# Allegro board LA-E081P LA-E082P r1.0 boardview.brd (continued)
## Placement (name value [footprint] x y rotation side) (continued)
CZ121  470P_0402_50V7K  [C_0402]  270.52 48.23 270 top
CZ122  0.1U_0201_10V6K  [C_0201]  192.96 14.5 180 top
CZ124  2200P_0402_50V7K  [C_0402]  277.32 47.39 180 bottom
CZ125  0.1U_0201_10V6K  [C_0201]  277.25 73.39 90 top
CZ126  220P_0402_50V7K  [C_0402]  275.72 71.09 270 top
CZ127  1000P_0402_50V7K  [C_0402]  274.71 71.09 270 top
CZ128  0.1U_0201_10V6K  [C_0201]  272.93 73.55 90 top
CZ129  0.1U_0201_10V6K  [C_0201]  279.95 39.96 180 bottom
CZ130  470P_0402_50V7K  [C_0402]  281.31 41.5 270 bottom
CZ133  0.1U_0201_10V6K  [C_0201]  289.18 62.63 90 bottom
CZ134  0.01UF_0402_25V7K  [C_0402]  283.8 66.95 180 top
CZ135  0.22U_0402_10V6K  [C_0402]  282.88 65.99 0 top
CZ136  0.22U_0402_10V6K  [C_0402]  282.88 65.04 0 top
CZ141  0.22U_0402_10V6K  [C_0402]  282.88 63.14 0 top
CZ142  0.22U_0402_10V6K  [C_0402]  282.88 64.09 0 top
CZ197  470P_0402_50V7K  [C_0402]  270.69 53.36 0 top
CZ198  100P_0402_50V8J  [C_0402]  291.47 50.51 270 top
DA1  AZ5123-02S.R7G_SOT23-3  [L03ESDL5V0CC3-2_SOT23-3]  311.82 35.07 90 top
DA2  -  [L03ESDL5V0CC3-2_SOT23-3]  311.82 31.01 90 top
DA3  AZ5123-02S.R7G_SOT23-3  [L03ESDL5V0CC3-2_SOT23-3]  309.73 39.13 270 top
DA6  -  [L03ESDL5V0CC3-2_SOT23-3]  284.08 29.74 270 top
DA7  -  [L03ESDL5V0CC3-2_SOT23-3]  284.08 34.31 270 top
DA8  RB751S40T1G_SOD523-2  [RB520SM-30T2R_EMD2-2]  293.81 42.02 0 top
DE1  RB751S40T1G_SOD523-2  [RB520SM-30T2R_EMD2-2]  267.18 39.09 220 top
DI1  -  [L05ESDL5V0NA-4_SLP2510P8-10-9]  19.94 70.38 270 top
DI2  -  [AZC199-02SPR7G_SOT23-3]  24.14 71.27 270 top
DI3  -  [AZC199-02SPR7G_SOT23-3]  80.46 101.72 180 bottom
DI4  -  [L05ESDL5V0NA-4_SLP2510P8-10-9]  308.81 54.87 90 top
DI5  -  [AZC199-02SPR7G_SOT23-3]  309.12 50.82 180 top
DI6  -  [L05ESDL5V0NA-4_SLP2510P8-10-9]  80.41 102.2 180 top
DT1  -  [1N4148WS-7-F_SOD323-2]  38.67 98.57 180 bottom
DT2  -  [1N4148WS-7-F_SOD323-2]  38.67 96.79 180 bottom
DT3  -  [1N4148WS-7-F_SOD323-2]  35.69 94.45 270 bottom
DT4  -  [L30ESD24VC3-2_SOT23-3]  12.83 90.21 0 bottom
DT5  ESD8011MUT5G_X3DFN2-2  [ESD8011MUT5G_X3DFN2-2-S]  11.86 94.2 270 bottom
DT6  ESD8011MUT5G_X3DFN2-2  [ESD8011MUT5G_X3DFN2-2-S]  11.86 95.04 90 bottom
DT7  ESD8011MUT5G_X3DFN2-2  [ESD8011MUT5G_X3DFN2-2-S]  11.85 94.31 270 top
DT8  ESD8011MUT5G_X3DFN2-2  [ESD8011MUT5G_X3DFN2-2-S]  11.83 97.85 90 top
DT9  ESD8011MUT5G_X3DFN2-2  [ESD8011MUT5G_X3DFN2-2-S]  11.83 100.05 270 bottom
DT10  ESD8011MUT5G_X3DFN2-2  [ESD8011MUT5G_X3DFN2-2-S]  11.83 100.9 90 bottom
DT11  ESD8011MUT5G_X3DFN2-2  [ESD8011MUT5G_X3DFN2-2-S]  11.86 97.03 270 bottom
DT12  ESD8011MUT5G_X3DFN2-2  [ESD8011MUT5G_X3DFN2-2-S]  11.83 97.85 90 bottom
DT13  ESD8011MUT5G_X3DFN2-2  [ESD8011MUT5G_X3DFN2-2-S]  11.4 91.42 270 bottom
DT14  ESD8011MUT5G_X3DFN2-2  [ESD8011MUT5G_X3DFN2-2-S]  11.4 92.26 90 bottom
DT15  ESD8011MUT5G_X3DFN2-2  [ESD8011MUT5G_X3DFN2-2-S]  11.86 97.03 270 top
DT16  ESD8011MUT5G_X3DFN2-2  [ESD8011MUT5G_X3DFN2-2-S]  11.86 95.04 90 top
DT17  ESD8011MUT5G_X3DFN2-2  [ESD8011MUT5G_X3DFN2-2-S]  11.83 100.9 90 top
DT18  ESD8011MUT5G_X3DFN2-2  [ESD8011MUT5G_X3DFN2-2-S]  11.83 100.05 270 top
DT19  ESD8011MUT5G_X3DFN2-2  [ESD8011MUT5G_X3DFN2-2-S]  11.85 92.26 90 top
DT20  ESD8011MUT5G_X3DFN2-2  [ESD8011MUT5G_X3DFN2-2-S]  11.84 91.42 270 top
DV1  -  [BAT54CW_SOT323-3]  105.67 86.12 180 bottom
DV2  -  [BAT54CW_SOT323-3]  103.13 85.87 180 bottom
DV3  -  [BAT54CW_SOT323-3]  92.97 83.78 0 bottom
DV4  -  [AZC199-02SPR7G_SOT23-3]  116.44 87.33 90 bottom
DV5  -  [PJDLC05C_SOT23-3]  314.3 85.04 90 bottom
DV6  -  [PJDLC05C_SOT23-3]  314.3 80.98 90 bottom
DZ1  RB751S40T1G_SOD523-2  [RB520SM-30T2R_EMD2-2]  216.57 9.38 180 top
DZ2  RB751S40T1G_SOD523-2  [RB520SM-30T2R_EMD2-2]  216.57 10.65 180 top
DZ5  RB751S40T1G_SOD523-2  [RB520SM-30T2R_EMD2-2]  292.83 49.17 90 top
DZ6  RB751S40T1G_SOD523-2  [RB520SM-30T2R_EMD2-2]  293.53 45.75 90 top
DZ7  RB751S40T1G_SOD523-2  [RB520SM-30T2R_EMD2-2]  221.31 22.52 180 top
FD1  FIDUCIAL MARK~D  [FIDUCIAL_C40M80]  315.36 95.48 0 top
FD2  FIDUCIAL MARK~D  [FIDUCIAL_C40M80]  15.37 3.83 0 top
FD3  FIDUCIAL MARK~D  [FIDUCIAL_C40M80]  15.37 3.83 180 bottom
FD4  FIDUCIAL MARK~D  [FIDUCIAL_C40M80]  323.22 97.3 180 bottom
H1  -  [H_3P8]  87.65 73.4 0 top
H2  -  [H_3P8]  87.65 45.4 0 top
H3  -  [H_3P8]  144.25 81.75 0 top
H4  -  [H_3P8]  149.15 47.45 0 top
H5  -  [H_1P1N]  98.5 71.86 0 top
H6  -  [H_1P1N]  139.62 48.75 0 top
H7  -  [H_3P2]  234.9 15.5 0 top
H8  -  [H_3P2]  296.05 87.5 0 top
H9  H_2P3  [H_2P3-G]  141.95 118.9 0 top
H10  H_3P0  [H_3P0-G]  310.15 98.9 0 top
H12  H_2P5  [H_2P5-G]  323.65 22.4 0 top
H14  H_4P0  [H_4P0-G]  267.65 58.9 0 top
H15  H_4P0  [H_4P0-G]  269.65 101.4 0 top
H16  H_2P3  [H_2P3-G]  67.35 116.9 0 top
H17  H_4P0  [H_4P0-G]  113.15 2.1 0 top
H18  H_2P5  [H_2P5-G]  4.45 3 0 top
H20  H_4P0  [H_4P0-G]  202.75 37.1 0 top
H22  H_4P0  [H_4P0-G]  241 1.5 0 top
H23  H_2P5  [H_2P5-G]  6.25 106.1 0 top
H24  H_2P5  [H_2P5-G]  6.25 88 0 top
H25  H_2P2  [H_2P2-G]  4.45 8.4 0 top
H26  H_2P3  [H_2P3-G]  116.55 116.9 0 top
H28  H_2P5  [H_2P5-G]  268.15 106.3 0 top
H29  H_2P5  [H_2P5-G]  282.15 110.4 0 top
H32  H_2P6X3P6  [H_2P6X3P6-G]  318.05 22.4 90 top
H34  -  [H_3P2]  89.35 94.4 0 top
H35  -  [H_3P2]  123.75 94.4 0 top
H38  -  [H_3P8]  147.55 117.4 0 top
H42  -  [H_0P7N]  121.59 116.25 0 top
H43  -  [H_0P9N]  130.79 103.2 0 top
JAPS1  ACES_50506-01841-P01  [ACES_50506-01841-P01_18P]  317.63 62.25 90 bottom
JCRT1  CCM_C070546HR015M29CZR  [CCM_C070546HR015M29CZR_15P-T]  322.15 83.18 90 bottom
JDB1  JXT_FP241AH-006GAAM  [JXT_FP241AH-006GAAM_6P]  32.37 97.09 180 top
JDEG1  JXT_FP241AH-010GAAM  [JXT_FP241AH-010GAAM_10P]  275.98 77.9 270 bottom
JDIMM1  LCN_DAN05-Q0406-0103  [LCN_DAN05-Q0406-0103_260P]  39.28 13 180 bottom
JDIMM2  LCN_DAN05-Q0406-0103  [LCN_DAN05-Q0406-0103_260P]  120.28 13 180 bottom
JEDP1  ACES_50398-04041-001  [ACES_50398-04041-001_40P]  116.3 92.14 180 bottom
JESPI  JXT_FP241AH-010GAAM  [JXT_FP241AH-010GAAM_10P]  269.76 70.34 270 bottom
JFAN1  ACES_50271-0040N-001  [ACES_50271-0040N-001_4P]  267.69 44.49 50 bottom
JHDMI1  CONCR_099BKAC19YBLCNF  [CONCR_099BKAC19YBLCNF_19P]  98.55 111.32 0 bottom
JHP1  SINGA_2SJ3095-136111F  [SINGA_2SJ3095-136111F_7P-T]  316.45 38.4 90 bottom
JIR1  ACES_50208-0060N-P01  [ACES_50208-0060N-P01_6P]  76.83 92.5 90 bottom
JKBTP1  CVILU_CF5020FD0RK-05-NH  [CVILU_CF5020FD0RK-05-NH_20P-T]  213.13 22.65 270 top
JLED1  CVILU_CF5006FD0R0-05-NH  [CVILU_CF5006FD0R0-05-NH_6P]  284.4 51.15 0 top
JLOM1  SANTA_130456-831  [SANTA_130456-831_13P-T]  292.98 107.18 0 bottom
JNGFF1  BELLW_80148-4221  [BELLW_80148-4221_67P]  201.27 24.75 270 bottom
JNGFF2  BELLW_80149-4221  [BELLW_80149-4221_67P]  286.8 41.87 0 bottom
JNGFF3  LCN_DAN05-67356-0103  [LCN_DAN05-67356-0103_75P]  307.95 33.92 180 bottom
JRTC1  ACES_50271-0020N-001  [ACES_50271-0020N-001_2P]  61.25 78.28 90 bottom
JSATA1  ACES_59003-02006-002  [ACES_59003-02006-002_20P]  271.9 34.63 0 bottom
JSD1  T-SOL_156-2000302608_NR  [T-SOL_156-2000302608_19P_NR]  32.38 40.5 90 bottom
JSIM1  T-SOL_5-991503004000-6  [T-SOL_5-991503004000-6_8P-T]  123.74 105.88 0 bottom
JSPI1  E-T_6705K-Y20N-00L  [E-T_6705K-Y20N-00L_20P]  157.85 46.93 180 bottom
JSPK1  ACES_50278-00401-001  [ACES_50278-00401-001_4P]  264.99 29.6 90 top
JTAG1  @SHORT PADS~D  [SHORTPADS]  299.73 87.62 90 top
JUART1  CVILU_CI1804M1VRA-NH  [CVILU_CI1804M1VRA-NH_4P]  45.26 62.29 270 bottom
JUSB1  C-K_26230A-8K1A-02  [C-K_26230A-8K1A-02_9P-T]  313.1 46.35 270 bottom
JUSB2  LOTES_AUSB0014-P003A  [LOTES_AUSB0014-P003A_9P]  15.66 77.9 90 bottom
JUSB3  C-K_26210B-8K1A-02  [C-K_26210B-8K1A-02_9P]  84.05 107.02 0 bottom
JUSBC1  JAE_DX07BD24JJ2  [JAE_DX07BD24JJ2_24P-T]  7.55 94.43 90 bottom
JUSH1  CVILU_CF5026FD0RK-05-NH  [CVILU_CF5026FD0RK-05-NH_26P-T]  222.97 7.15 90 top
JXDP1  SAMTE_BSH-030-01-L-D-A  [SAMTE_BSH-030-01-L-D-A_60P]  75.45 35.84 180 top
LA5  BLM15PX600SN1D_2P  [MURAT_BLM15PX600SN1D_2P]  307.54 28.57 270 top
LA6  BLM15PD800SN1D_2P  [MURAT_BLM15PD800SN1D_2P]  288.86 30.05 180 top
LA7  BLM15PD800SN1D_2P  [MURAT_BLM15PD800SN1D_2P]  288.86 31.13 180 top
LA8  BLM15PD800SN1D_2P  [MURAT_BLM15PD800SN1D_2P]  288.87 36.76 270 top
LA9  BLM15PD800SN1D_2P  [MURAT_BLM15PD800SN1D_2P]  286.89 36.85 180 top
LA10  BLM15PX330SN1D_2P  [MURAT_BLM15PX330SN1D_2P]  309.38 39.13 0 bottom
LA11  BLM15PX330SN1D_2P  [MURAT_BLM15PX330SN1D_2P]  309.38 36.59 0 bottom
LA12  BLM15PX600SN1D_2P  [MURAT_BLM15PX600SN1D_2P]  294.5 32.78 180 top
LA13  HCB2012VF-601T20_2P  [TAI-T_HCB2012VF-601T20_2P]  300.17 43.47 90 top
LA14  BLM15PX600SN1D_2P  [MURAT_BLM15PX600SN1D_2P]  293.46 40.95 0 top
LA15  BLM15PX330SN1D_2P  [MURAT_BLM15PX330SN1D_2P]  308.02 37.41 90 top
LA16  BLM15PX330SN1D_2P  [MURAT_BLM15PX330SN1D_2P]  307.99 36.54 270 top
LC1  BLM15GA750SN1D_2P  [MURAT_BLM15GA750SN1D_2P]  126.5 33.4 270 top
LC2  BLM15GA750SN1D_2P  [MURAT_BLM15GA750SN1D_2P]  145.29 62.44 180 top
LED3  LTW-C193DC-C_WHITE  [LED_LTW-C193DC-C_2P]  320.9 98.51 180 top
LGA1  -  [LNG2DMTR_LGA12_2X2]  273.72 45.23 270 bottom
LI3  EXC24CQ900U_4P  [PANAS_EXC24CQ900U_4P]  29.72 69.87 270 top
LI4  EXC24CQ900U_4P  [PANAS_EXC24CQ900U_4P]  77.35 100.09 270 bottom
LI7  EXC24CQ900U_4P  [PANAS_EXC24CQ900U_4P]  308.44 45.62 180 top
LI8  MCM1012B900F06BP_4P  [INPAQ_MCM1012B900F06BP_4P]  290.2 45.6 270 top
LI9  MCM1012B900F06BP_4P  [INPAQ_MCM1012B900F06BP_4P]  197.57 23.64 0 bottom
LI16  HCM1012GH900BP_4P  [INPAQ_HCM1012GH900BP_4P]  292.23 45.6 270 top
LI17  HCM1012GH900BP_4P  [INPAQ_HCM1012GH900BP_4P]  295.4 47.57 270 top
LL1  4.7UH_BRC2012T4R7MD_20%  [TAIYO_BRC2012T4R7MD_2P]  283.56 86.38 0 top
LT11  BLM15PX600SN1D_2P  [MURAT_BLM15PX600SN1D_2P]  19.69 89.05 90 top
LV1  BLM15PX221SN1D_2P  [MURAT_BLM15PX221SN1D_2P]  106.94 88.9 270 bottom
LV3  HCM1012GH900BP_4P  [TAIYO_MCF12102G900-T_4P-NPM]  98.41 104.23 90 top
LV6  HCM1012GH900BP_4P  [TAIYO_MCF12102G900-T_4P-NPM]  101.96 104.23 90 top
LV9  HCM1012GH900BP_4P  [TAIYO_MCF12102G900-T_4P-NPM]  108.31 104.23 90 top
LV12  HCM1012GH900BP_4P  [TAIYO_MCF12102G900-T_4P-NPM]  105.52 104.23 90 top
LV14  BLM15PX600SN1D_2P  [MURAT_BLM15PX600SN1D_2P]  275.6 55.39 90 bottom
LV16  BLM15BB470SN1D_2P  [MURAT_BLM15BB470SN1D_2P]  317.38 89.48 270 bottom
LV17  BLM15BB470SN1D_2P  [MURAT_BLM15BB470SN1D_2P]  316.11 89.48 270 bottom
LV18  BLM15BB470SN1D_2P  [MURAT_BLM15BB470SN1D_2P]  313.44 76.01 90 bottom
LV19  BLM15AG121SN1D_L0402_2P  [MURAT_BLM15AG121SN1D_L0402_2P]  316.62 77.76 90 top
LV20  BLM15AG121SN1D_L0402_2P  [MURAT_BLM15AG121SN1D_L0402_2P]  316.62 75.47 90 top
LV27  EXC24CQ900U_4P  [PANAS_EXC24CQ900U_4P]  120.66 86.27 270 bottom
LV30  BLM15PX600SN1D_2P  [MURAT_BLM15PX600SN1D_2P]  281.72 56.08 270 top
LZ1  EXC24CQ900U_4P  [PANAS_EXC24CQ900U_4P]  110.88 87.52 0 bottom
NOREF  -  []  323.65 22.4 0 top
NOREF#2  -  []  186.38 29.29 0 top
NOREF#3  -  []  4.45 8.4 0 top
NOREF#4  -  []  141.95 118.9 0 top
NOREF#5  -  []  87.65 73.4 0 top
NOREF#6  -  []  113.15 2.1 0 top
NOREF#7  -  []  296.05 87.5 0 top
NOREF#8  -  []  6.25 106.1 0 top
NOREF#9  -  []  6.25 88 0 top
NOREF#10  -  []  65.41 -32.24 0 top
NOREF#11  -  []  168.09 76.17 0 top
NOREF#12  -  []  89.63 31.42 0 top
NOREF#13  -  []  282.15 110.4 0 top
NOREF#14  -  []  147.55 117.4 0 top
NOREF#15  -  []  108.27 26.24 90 top
NOREF#16  -  []  72.27 161.56 0 top
NOREF#17  -  []  4.45 3 0 top
NOREF#18  -  []  310.15 98.9 0 top
NOREF#19  -  []  144.25 81.75 0 top
NOREF#20  -  []  145.04 20.91 0 top
NOREF#21  -  []  317.55 22.4 0 top
NOREF#22  -  []  87.44 26.31 0 top
NOREF#23  -  []  149.15 47.45 0 top
NOREF#24  -  []  67.35 116.9 0 top
NOREF#25  -  []  116.55 116.9 0 top
NOREF#26  -  []  234.9 15.5 0 top
NOREF#27  -  []  4.45 8.4 0 top
NOREF#28  -  []  4.45 8.4 0 top
NOREF#29  -  []  269.65 101.4 0 top
NOREF#30  -  []  41.75 18.36 0 top
NOREF#31  -  []  268.15 106.3 0 top
NOREF#32  -  []  202.75 37.1 0 top
NOREF#33  -  []  267.65 58.9 0 top
NOREF#34  -  []  87.65 45.4 0 top
NOREF#35  -  []  241 1.5 0 top
NOREF#36  -  []  81.58 28.4 180 bottom
NOREF#37  -  []  171.96 86.63 180 bottom
NOREF#38  -  []  129.42 24.4 180 bottom
PBATT1  DEREN_40-42251-01001RHF  [DEREN_40-42251-01001RHF_10P-T]  26 12.35 180 bottom
PC1  2200P_0402_50V7K  [C_0402]  22.61 7.46 270 top
PC2  2200P_0402_50V7K  [C_0402]  63.01 78.98 270 top
PC3  1U_0603_25V6K  [C_0603]  58.39 77.53 90 top
PC4  0.022U_0603_50V7K  [C_0603]  46.77 80.85 0 top
PC5  1000P_0603_50V7K  [C_0603]  54.62 87.74 180 bottom
PC6  0.022U_0603_50V7K  [C_0603]  48.98 91.17 0 top
PC7  0.1U_0603_25V7K  [C_0603]  53.78 89.06 270 top
PC8  10U_0805_25V6K  [C_0805]  52.3 86.08 0 top
PC9  0.1U_0402_10V7K  [C_0402]  61.84 96.75 90 bottom
PC10  2.2U_0402_10V6M  [C_0402]  73.78 104.73 0 top
PC11  1U_0603_50V6K  [C_0603]  73.84 100.89 0 top
PC100  100P_0402_50V8J  [C_0402]  157.25 117.58 180 bottom
PC102  0.1U_0603_25V7K  [C_0603]  159.77 110.25 180 top
PC103  100P_0402_50V8J  [C_0402]  157.26 117.58 180 top
PC104  10U_0805_25V6K  [C_0805]  157.19 115.59 180 bottom
PC105  10U_0805_25V6K  [C_0805]  157.19 115.59 180 top
PC106  22UF_0805_6.3V6M  [C_0805]  149.36 106.44 90 bottom
PC107  22UF_0805_6.3V6M  [C_0805]  151.14 104.26 90 bottom
PC108  22UF_0805_6.3V6M  [C_0805]  152.85 104.26 90 top
PC109  22UF_0805_6.3V6M  [C_0805]  149.36 106.44 90 top
PC110  22UF_0805_6.3V6M  [C_0805]  152.85 104.26 90 bottom
PC111  4.7U_0603_6.3V6K  [C_0603]  154.27 109.06 180 top
PC112  680P_0603_50V7K  [C_0603]  160.57 108.73 270 bottom
PC113  1000P_0402_50V7K  [C_0402]  152.45 112.46 180 top
PC114  0.1U_0603_25V7K  [C_0603]  162.33 112 0 bottom
PC115  100P_0402_50V8J  [C_0402]  163.38 117.53 90 bottom
PC116  100P_0402_50V8J  [C_0402]  163.33 117.63 90 top
PC117  10U_0805_25V6K  [C_0805]  164.43 117.99 0 bottom
PC118  10U_0805_25V6K  [C_0805]  164.47 118.1 0 top
PC119  4.7U_0603_6.3V6K  [C_0603]  170.63 111.65 0 bottom
PC120  22UF_0805_6.3V6M  [C_0805]  170.95 101.06 0 top
PC121  22UF_0805_6.3V6M  [C_0805]  170.92 102.84 0 top
PC122  22UF_0805_6.3V6M  [C_0805]  170.95 104.59 0 top
PC123  22UF_0805_6.3V6M  [C_0805]  171.24 101.05 0 bottom
PC124  22UF_0805_6.3V6M  [C_0805]  171.24 102.82 0 bottom
PC125  680P_0603_50V7K  [C_0603]  162.5 106.76 270 bottom
PC126  4.7U_0603_6.3V6K  [C_0603]  170.63 112.86 0 bottom
PC127  1000P_0402_50V7K  [C_0402]  171.17 114.63 0 bottom
PC128  4.7U_0402_6.3V6M  [C_0402]  171.03 115.5 90 bottom
PC129  22UF_0805_6.3V6M  [C_0805]  151.14 104.26 90 top
PC130  22UF_0805_6.3V6M  [C_0805]  171.24 104.6 0 bottom
PC131  82P_0402_50V8J  [C_0402]  157.24 118.53 180 bottom
PC132  82P_0402_50V8J  [C_0402]  164.23 119.33 180 bottom
PC200  10U_0805_25V6K  [C_0805]  42.31 47.63 90 bottom
PC201  10U_0805_25V6K  [C_0805]  42.98 47.6 90 top
PC202  0.1U_0402_25V6  [C_0402]  40.7 47.89 90 bottom
PC203  2200P_0402_50V7K  [C_0402]  40.76 47.87 90 top
PC204  680P_0603_50V7K  [C_0603]  47.51 48.98 180 top
PC205  0.1U_0603_16V7K  [C_0603]  49.63 47.44 0 top
PC206  1U_0402_6.3V6K  [C_0402]  47.55 45.63 270 bottom
PC207  2.2U_0402_6.3V6M  [C_0402]  46.69 45.64 270 bottom
PC208  330P_0402_50V7K  [C_0402]  44.65 44.65 90 bottom
PC209  22U_0603_6.3V6M  [C_0603]  47.76 51.23 90 bottom
PC210  22U_0603_6.3V6M  [C_0603]  56.86 42.01 0 top
PC211  22U_0603_6.3V6M  [C_0603]  47.81 42.02 90 bottom
PC212  22U_0603_6.3V6M  [C_0603]  56.87 43.22 0 top
PC213  22U_0603_6.3V6M  [C_0603]  56.87 43.22 0 bottom
PC214  10U_0603_6.3V6M  [C_0603]  56.87 42.01 0 bottom
PC216  2200P_0402_50V7K  [C_0402]  56.93 44.52 0 top
PC217  100P_0402_50V8J  [C_0402]  45.55 43.79 180 bottom
PC218  1U_0402_10V6K  [C_0402]  44.98 51.14 90 bottom
PC219  22U_0603_6.3V6M  [C_0603]  46.52 51.23 90 bottom
PC221  0.1U_0402_10V7K  [C_0402]  40.59 51.15 90 bottom
PC222  0.1U_0402_10V7K  [C_0402]  43.21 51.15 90 bottom
PC223  10U_0603_6.3V6M  [C_0603]  56.86 44.42 0 bottom
PC301  100P_0402_50V8J  [C_0402]  179.13 97.43 0 top
PC302  680P_0603_50V7K  [C_0603]  174.57 91.78 90 bottom
PC303  100P_0402_50V8J  [C_0402]  179.13 97.43 0 bottom
PC304  0.1U_0603_25V7K  [C_0603]  177.87 93.17 180 bottom
PC305  10U_0603_25V6M  [C_0603]  179.2 98.51 0 top
PC306  10U_0603_25V6M  [C_0603]  179.2 98.51 0 bottom
PC307  330P_0402_50V7K  [C_0402]  185.93 93.1 90 bottom
PC308  22U_0603_6.3V6M  [C_0603]  183.39 82.12 0 bottom
PC309  22U_0603_6.3V6M  [C_0603]  183.39 80.92 0 bottom
PC310  22U_0603_6.3V6M  [C_0603]  183.39 83.33 0 bottom
PC311  22U_0603_6.3V6M  [C_0603]  183.39 79.71 0 bottom
PC312  4.7U_0603_6.3V6K  [C_0603]  184.28 91.9 0 bottom
PC313  4.7U_0603_6.3V6K  [C_0603]  184.28 90.7 0 bottom
PC314  82P_0402_50V8J  [C_0402]  179.2 99.62 0 bottom
PC401  470P_0402_50V7K  [C_0402]  137.41 107.73 0 top
PC402  0.1U_0402_25V6  [C_0402]  137.46 111.41 180 top
PC403  10U_0603_10V6M  [C_0603]  138.45 113.66 90 top
PC404  10U_0603_10V6M  [C_0603]  139.7 113.67 90 top
PC406  22U_0603_6.3V6M  [C_0603]  143.61 104.81 90 top
PC407  22U_0603_6.3V6M  [C_0603]  139.59 103.68 270 top
PC408  0.1U_0402_25V6  [C_0402]  141.69 113.37 90 top
PC409  100P_0402_50V8J  [C_0402]  140.77 113.36 90 top
PC410  470P_0402_50V7K  [C_0402]  144.71 111.42 0 top
PC411  0.1U_0402_25V6  [C_0402]  127.92 113.77 90 top
PC412  10U_0603_10V6M  [C_0603]  131.11 115.59 90 top
PC413  10U_0603_10V6M  [C_0603]  132.33 115.6 90 top
PC415  22U_0603_6.3V6M  [C_0603]  131.38 106.1 270 top
PC416  22U_0603_6.3V6M  [C_0603]  133.43 107.06 0 top
PC417  0.1U_0402_25V6  [C_0402]  130.03 116.43 180 top
PC418  2200P_0402_50V7K  [C_0402]  130.04 115.55 180 top
PC419  470P_0402_50V7K  [C_0402]  127 110.11 0 top
PC420  470P_0402_50V7K  [C_0402]  133.72 112.29 0 top
PC422  22U_0603_6.3V6M  [C_0603]  140.82 103.67 270 top
PC424  22U_0603_6.3V6M  [C_0603]  130.13 106.08 270 top
PC501  22U_0603_6.3V6M  [C_0603]  119.71 103.27 90 top
PC502  22U_0603_6.3V6M  [C_0603]  125.33 107.43 90 top
PC503  68P_0402_50V8J  [C_0402]  120.53 109.67 0 top
PC504  22U_0603_6.3V6M  [C_0603]  120.94 103.26 90 top
PC505  0.1U_0402_16V7K  [C_0402]  120.61 105.84 180 top
PC506  680P_0402_50V7K  [C_0402]  126.04 106.47 180 top
PC513  .1U_0402_16V7K  [C_0402]  197.61 3.11 270 top
PC514  4.7U_0603_6.3V6K  [C_0603]  196.56 6.33 180 top
PC515  0.01UF_0402_25V7K  [C_0402]  191.01 4.17 0 top
PC516  22U_0603_6.3V6M  [C_0603]  192.24 6.45 0 top
PC601  680P_0402_50V7K  [C_0402]  65.6 43.79 90 bottom
PC602  0.1U_0402_25V6  [C_0402]  72.04 50.72 180 bottom
PC603  1U_0603_10V6K  [C_0603]  74.37 47.96 0 top
PC604  0.22U_0603_25V7K  [C_0603]  72.65 47.92 0 bottom
PC605  47P_0402_50V8J~D  [C_0402]  74.43 52.61 270 top
PC606  100U_D_20VM_R55M  [C_D]  50.82 70.08 180 bottom
PC608  10U_0805_25V6K  [C_0805]  70.31 78.37 270 bottom
PC611  0.22U_0603_16V7K  [C_0603]  65.73 78.38 0 top
PC612  10U_0805_25V6K  [C_0805]  70.5 78.36 270 top
PC613  330P_0402_50V7K  [C_0402]  70.03 52.37 90 bottom
PC614  2200P_0402_50V7K  [C_0402]  67.39 52.37 90 bottom
PC616  68P_0402_50V8J  [C_0402]  68.25 52.32 0 bottom
PC617  1200P_0402_50V7K  [C_0402]  69.54 57.85 0 top
PC618  330P_0402_50V7K  [C_0402]  70.47 56.1 180 bottom
PC619  0.01UF_0402_25V7K  [C_0402]  70.47 55.19 180 bottom
PC620  0.082U_0402_16V7K  [C_0402]  68.64 56.04 270 top
PC621  680P_0402_50V7K  [C_0402]  71.3 56.14 270 top
PC622  680P_0603_50V7K  [C_0603]  72.55 78.19 270 top
PC624  0.033U_0402_16V7K  [C_0402]  65.99 55.18 90 bottom
PC625  330P_0402_50V7K  [C_0402]  66.5 50.91 180 bottom
PC626  0.047U_0402_25V7K  [C_0402]  66.88 55.18 90 bottom
PC627  2200P_0402_50V7K  [C_0402]  65.99 56.06 270 top
PC628  33P_0402_50V8J  [C_0402]  69.89 47.07 90 bottom
PC629  2200P_0402_50V7K  [C_0402]  65.02 46.35 180 bottom
PC630  2200P_0402_50V7K  [C_0402]  62.79 46.12 180 top
PC631  4700P_0402_25V7K  [C_0402]  71.75 48.09 180 bottom
PC632  1000P_0402_50V7K  [C_0402]  71.77 44.79 0 top
PC633  3300P_0402_25V7K  [C_0402]  71.81 42.13 90 top
PC636  68P_0402_50V8J  [C_0402]  65.01 47.2 90 bottom
PC637  0.033U_0402_16V7K  [C_0402]  73.53 42.13 90 top
PC639  2200P_0402_50V7K  [C_0402]  61.81 52.46 180 top
PC640  2200P_0402_50V7K  [C_0402]  68.24 42.91 90 bottom
PC641  .1U_0402_16V7K  [C_0402]  66.89 57.08 180 bottom
PC642  0.033U_0402_16V7K  [C_0402]  62.79 48.76 270 top
PC643  330P_0402_50V7K  [C_0402]  68.97 47.05 90 bottom
PC644  .1U_0402_16V7K  [C_0402]  74.44 43.87 90 top
PC645  .1U_0402_16V7K  [C_0402]  60.13 47 270 top
PC646  0.047U_0402_25V7K  [C_0402]  61.9 48.76 270 top
PC647  680P_0402_50V7K  [C_0402]  60.97 54.45 0 top
PC649  0.01UF_0402_25V7K  [C_0402]  69.99 43.83 270 bottom
PC650  0.082U_0402_16V7K  [C_0402]  69.07 44.71 0 bottom
PC651  330P_0402_50V7K  [C_0402]  60.97 51.33 0 top
PC652  330P_0402_50V7K  [C_0402]  69.11 43.83 270 bottom
PC653  0.082U_0402_16V7K  [C_0402]  62.74 50.95 270 top
PC654  0.01UF_0402_25V7K  [C_0402]  60.88 50.06 0 top
PC655  0.22U_0603_16V7K  [C_0603]  56.88 71.84 0 top
PC656  10U_0805_25V6K  [C_0805]  53.8 70.49 90 bottom
PC657  10U_0805_25V6K  [C_0805]  55.51 70.48 90 bottom
PC658  10U_0805_25V6K  [C_0805]  55.52 70.48 90 top
PC659  100P_0402_50V8J  [C_0402]  57.02 68.61 0 top
PC660  82P_0402_50V8J  [C_0402]  57 69.51 0 top
PC661  1U_0402_10V6K  [C_0402]  61.69 71.74 270 top
PC662  680P_0603_50V7K  [C_0603]  64.65 72.92 90 top
PC663  10U_0805_25V6K  [C_0805]  53.73 70.5 90 top
PC664  10U_0805_25V6K  [C_0805]  54.74 63.39 270 top
PC665  10U_0805_25V6K  [C_0805]  54.74 63.39 270 bottom
PC671  0.22U_0603_16V7K  [C_0603]  54.87 66.44 0 top
PC672  10U_0805_25V6K  [C_0805]  56.54 63.45 270 bottom
PC673  10U_0805_25V6K  [C_0805]  56.54 63.45 270 top
PC677  1U_0402_10V6K  [C_0402]  61.73 64.84 90 top
PC678  680P_0603_50V7K  [C_0603]  67.7 68.6 180 top
PC679  1000P_0402_50V7K  [C_0402]  53.35 62.64 270 top
PC680  1000P_0402_50V7K  [C_0402]  57.01 67.72 0 top
PC685  1U_0402_10V6K  [C_0402]  68.58 74.88 0 bottom
PC686  10P_0402_50V8K  [C_0402]  56.9 71.14 90 bottom
PC688  10P_0402_50V8K  [C_0402]  53.34 62.65 270 bottom
PC902  0.1U_0402_25V6  [C_0402]  5.95 20.54 180 top
PC903  2200P_0402_50V7K  [C_0402]  4.83 25.21 90 bottom
PC904  22U_0805_25V6M  [C_0805]  6.13 23.57 180 bottom
PC905  22U_0805_25V6M  [C_0805]  6.13 21.84 180 top
PC906  22U_0805_25V6M  [C_0805]  6.13 21.85 180 bottom
PC909  15U_B2_25VM_R100M  [C_B2]  13.21 21.74 180 bottom
PC910  15U_B2_25VM_R100M  [C_B2]  10.09 26.09 270 bottom
PC911  22U_0805_25V6M  [C_0805]  6.13 23.58 180 top
PC913  10U_0805_25V6K  [C_0805]  28.96 13.73 90 top
PC914  10U_0805_25V6K  [C_0805]  35.54 18.74 180 top
PC915  10U_0805_25V6K  [C_0805]  35.22 10.9 270 top
PC916  10U_0805_25V6K  [C_0805]  30.74 13.73 90 top
PC917  10U_0805_25V6K  [C_0805]  32.9 13.73 90 top
PC918  10U_0805_25V6K  [C_0805]  35.54 17.03 180 top
PC919  10U_0805_25V6K  [C_0805]  31.77 10.9 270 top
PC920  10U_0805_25V6K  [C_0805]  33.5 10.9 270 top
PC925  4.7U_0402_6.3V6M  [C_0402]  16.2 21.27 0 top
PC926  1U_0402_25V6K  [C_0402]  15.35 22.11 90 top
PC927  1U_0402_25V6K  [C_0402]  18.01 22.12 90 top
PC928  0.1U_0402_25V6  [C_0402]  35.43 20.07 180 top
PC929  2200P_0402_50V7K  [C_0402]  35.44 21.07 180 top
PC930  0.22U_0603_25V7K  [C_0603]  20.83 23.32 270 top
PC931  1U_0603_25V6  [C_0603]  11.77 20.45 0 top
PC932  1U_0402_6.3V6K  [C_0402]  20.34 17.03 90 bottom
PC933  1U_0402_6.3V6K  [C_0402]  13.21 18.65 180 bottom
PC934  0.22U_0603_25V7K  [C_0603]  24.23 16.61 180 top
PC935  10U_0805_25V6K  [C_0805]  32.22 6.06 0 top
PC936  10U_0805_25V6K  [C_0805]  32.25 7.78 0 top
PC937  4700P_0402_25V7K  [C_0402]  28.2 8.02 270 top
PC938  10P_0402_50V8J  [C_0402]  13.55 12.44 180 top
PC939  0.1U_0402_25V6  [C_0402]  23.39 15.86 0 bottom
PC940  680P_0603_50V7K  [C_0603]  17.71 26.22 90 top
PC941  680P_0603_50V7K  [C_0603]  31.56 19.09 180 top
PC942  1U_0402_25V6K  [C_0402]  23.31 15.5 0 top
PC943  560P_0402_50V7K  [C_0402]  17.27 12.39 270 top
PC944  0.01UF_0402_25V7K  [C_0402]  16.37 10.63 0 top
PC945  4.7U_0402_6.3V6M  [C_0402]  22.46 13.74 90 top
PC946  1U_0402_25V6K  [C_0402]  23.37 12.85 0 top
PC947  0.1U_0402_25V6  [C_0402]  18.17 10.05 0 top
PC949  0.1U_0402_10V7K  [C_0402]  28.67 26.5 180 top
PC950  0.1U_0402_25V6  [C_0402]  20.99 11.49 90 top
PC951  15U_B2_25VM_R100M  [C_B2]  6.89 26.09 270 bottom
PC1001  22U_0603_6.3V6M  [C_0603]  112.48 62.4 180 top
PC1002  22U_0603_6.3V6M  [C_0603]  82.1 68.81 270 top
PC1003  22U_0603_6.3V6M  [C_0603]  113.61 60.81 90 top
PC1004  22U_0603_6.3V6M  [C_0603]  83.36 68.82 270 top
PC1005  22U_0603_6.3V6M  [C_0603]  118.54 58.59 0 top
PC1006  22U_0603_6.3V6M  [C_0603]  112.47 59.94 180 top
PC1007  22U_0603_6.3V6M  [C_0603]  113.6 56.07 90 top
PC1008  22U_0603_6.3V6M  [C_0603]  118.55 62.34 0 top
PC1009  22U_0603_6.3V6M  [C_0603]  88.04 66.34 270 top
PC1010  22U_0603_6.3V6M  [C_0603]  83.56 66.33 270 bottom
PC1011  22U_0603_6.3V6M  [C_0603]  112.47 63.63 180 top
PC1012  22U_0603_6.3V6M  [C_0603]  118.57 57.36 0 top
PC1013  22U_0603_6.3V6M  [C_0603]  83.36 67.42 90 bottom
PC1014  22U_0603_6.3V6M  [C_0603]  107.48 58.95 270 top
PC1015  22U_0603_6.3V6M  [C_0603]  108.56 60.1 0 top
PC1016  22U_0603_6.3V6M  [C_0603]  108.54 61.32 0 top
PC1017  22U_0603_6.3V6M  [C_0603]  108.67 57.59 0 top
PC1018  22U_0603_6.3V6M  [C_0603]  108.63 58.81 0 top
PC1019  22U_0603_6.3V6M  [C_0603]  103.75 63.68 0 top
PC1020  22U_0603_6.3V6M  [C_0603]  105.13 62.47 180 top
PC1021  22U_0603_6.3V6M  [C_0603]  107.46 61.46 270 top
PC1022  22U_0603_6.3V6M  [C_0603]  104.93 56.53 270 top
PC1023  22U_0603_6.3V6M  [C_0603]  102.48 64.75 180 top
PC1024  22U_0603_6.3V6M  [C_0603]  106.24 63.82 270 top
PC1025  22U_0603_6.3V6M  [C_0603]  107.44 63.82 270 top
PC1026  22U_0603_6.3V6M  [C_0603]  106.26 58.95 270 top
PC1027  22U_0603_6.3V6M  [C_0603]  107.42 56.5 270 top
PC1028  22U_0603_6.3V6M  [C_0603]  108.64 62.39 90 top
PC1029  22U_0603_6.3V6M  [C_0603]  109.97 63.81 270 top
PC1030  1U_0201_6.3V6M  [C_0201]  118.03 66.54 0 top
PC1031  1U_0201_6.3V6M  [C_0201]  119.26 65.02 90 top
PC1032  1U_0201_6.3V6M  [C_0201]  118.05 67.12 0 top
PC1033  1U_0201_6.3V6M  [C_0201]  118.28 64.97 90 top
PC1034  1U_0201_6.3V6M  [C_0201]  113.66 65.64 180 top
PC1035  1U_0201_6.3V6M  [C_0201]  111.43 57.17 180 top
PC1036  1U_0201_6.3V6M  [C_0201]  111.43 57.74 180 top
PC1037  1U_0201_6.3V6M  [C_0201]  113.67 68.09 180 top
PC1038  1U_0201_6.3V6M  [C_0201]  116.7 65.1 90 top
PC1039  1U_0201_6.3V6M  [C_0201]  117.3 65.08 90 top
PC1040  1U_0201_6.3V6M  [C_0201]  108.3 64.93 90 top
PC1041  1U_0201_6.3V6M  [C_0201]  106.43 64.92 90 top
PC1042  1U_0201_6.3V6M  [C_0201]  109.2 64.92 90 top
PC1043  1U_0201_6.3V6M  [C_0201]  103.7 64.94 90 top
PC1044  1U_0201_6.3V6M  [C_0201]  102.31 63.18 90 top
PC1045  1U_0201_6.3V6M  [C_0201]  100.65 57.96 270 top
PC1046  1U_0201_6.3V6M  [C_0201]  107.38 64.98 90 top
PC1047  1U_0201_6.3V6M  [C_0201]  101.49 61.63 180 top
PC1048  1U_0201_6.3V6M  [C_0201]  102.88 60.42 180 top
PC1049  1U_0201_6.3V6M  [C_0201]  101.07 63.16 90 top
PC1050  1U_0201_6.3V6M  [C_0201]  113.67 65.07 180 top
PC1051  1U_0201_6.3V6M  [C_0201]  118.74 63.28 0 top
PC1052  1U_0201_6.3V6M  [C_0201]  118.73 63.85 0 top
PC1053  1U_0201_6.3V6M  [C_0201]  118.54 55.9 0 top
PC1054  1U_0201_6.3V6M  [C_0201]  115 63.6 0 top
PC1055  1U_0201_6.3V6M  [C_0201]  102.38 61.05 180 top
PC1056  1U_0201_6.3V6M  [C_0201]  100.94 59.74 270 top
PC1057  22U_0603_6.3V6M  [C_0603]  84.59 79.77 90 top
PC1058  22U_0603_6.3V6M  [C_0603]  83.32 79.77 90 top
PC1059  22U_0603_6.3V6M  [C_0603]  122.5 63.56 180 top
PC1060  22U_0603_6.3V6M  [C_0603]  85.86 79.77 90 top
PC1061  22U_0603_6.3V6M  [C_0603]  86.78 66.33 270 top
PC1062  330U_D2_2.5VM_R9M  [C_D2]  75.29 73.17 270 bottom
PC1063  330U_D2_2.5VM_R9M  [C_D2]  75.25 63.1 270 bottom
PC1064  22U_0603_6.3V6M  [C_0603]  112.42 58.65 180 top
PC1065  22U_0603_6.3V6M  [C_0603]  112.46 61.19 180 top
PC1066  22U_0603_6.3V6M  [C_0603]  116.09 56.06 90 top
PC1067  22U_0603_6.3V6M  [C_0603]  82.12 71.46 270 top
PC1068  22U_0603_6.3V6M  [C_0603]  116.17 58.43 90 top
PC1069  22U_0603_6.3V6M  [C_0603]  114.89 62.19 270 top
PC1070  22U_0603_6.3V6M  [C_0603]  118.62 61.09 0 top
PC1071  22U_0603_6.3V6M  [C_0603]  118.56 59.84 0 top
PC1072  22U_0603_6.3V6M  [C_0603]  84.71 68.81 270 bottom
PC1073  22U_0603_6.3V6M  [C_0603]  117.32 57.45 270 top
PC1074  22U_0603_6.3V6M  [C_0603]  117.4 59.83 270 top
PC1075  22U_0603_6.3V6M  [C_0603]  112.34 57.51 270 top
PC1076  22U_0603_6.3V6M  [C_0603]  113.6 58.43 90 top
PC1077  22U_0603_6.3V6M  [C_0603]  114.85 57.46 270 top
PC1078  22U_0603_6.3V6M  [C_0603]  116.11 60.84 90 top
PC1079  22U_0603_6.3V6M  [C_0603]  117.34 62.21 270 top
PC1080  22U_0603_6.3V6M  [C_0603]  89.29 66.34 270 top
PC1081  22U_0603_6.3V6M  [C_0603]  80.88 71.42 270 top
PC1082  22U_0603_6.3V6M  [C_0603]  114.93 59.81 270 top
PC1083  1U_0201_6.3V6M  [C_0201]  111.44 56.6 180 top
PC1084  1U_0201_6.3V6M  [C_0201]  116.59 67.56 180 top
PC1085  1U_0201_6.3V6M  [C_0201]  118.02 67.73 0 top
PC1086  1U_0201_6.3V6M  [C_0201]  116.59 68.12 180 top
PC1087  1U_0201_6.3V6M  [C_0201]  119.23 66.29 90 top
PC1088  1U_0201_6.3V6M  [C_0201]  120.45 67.91 0 top
PC1089  1U_0201_6.3V6M  [C_0201]  115.78 65.1 90 top
PC1090  1U_0201_6.3V6M  [C_0201]  116.44 66.26 180 top
PC1091  1U_0201_6.3V6M  [C_0201]  114.87 54.27 0 top
PC1092  1U_0201_6.3V6M  [C_0201]  116.88 63.02 0 top
PC1093  1U_0201_6.3V6M  [C_0201]  116.88 63.59 0 top
PC1094  1U_0201_6.3V6M  [C_0201]  113.26 63.58 0 top
PC1095  1U_0201_6.3V6M  [C_0201]  118.55 56.47 0 top
PC1096  1U_0201_6.3V6M  [C_0201]  113.26 63.01 0 top
PC1097  1U_0201_6.3V6M  [C_0201]  116.58 67 180 top
PC1098  1U_0201_6.3V6M  [C_0201]  114.86 54.85 0 top
PC1099  1U_0201_6.3V6M  [C_0201]  116.86 53.61 180 top
PC1125  1U_0201_6.3V6M  [C_0201]  116.86 54.18 180 top
PC1126  1U_0201_6.3V6M  [C_0201]  115 63.03 0 top
PC1127  330U_D2_2.5VM_R9M  [C_D2]  80.02 73.17 270 bottom
PC1128  330U_D2_2.5VM_R9M  [C_D2]  80.02 63.1 270 bottom
PC1129  22U_0603_6.3V6M  [C_0603]  102.1 59.24 270 top
PC1130  22U_0603_6.3V6M  [C_0603]  108.67 56.36 0 top
PC1131  22U_0603_6.3V6M  [C_0603]  103.73 61.27 0 top
PC1132  22U_0603_6.3V6M  [C_0603]  106.22 61.48 270 top
PC1133  22U_0603_6.3V6M  [C_0603]  103.72 56.53 270 top
PC1134  22U_0603_6.3V6M  [C_0603]  105.12 60.07 180 top
PC1135  22U_0603_6.3V6M  [C_0603]  108.67 55.15 0 top
PC1136  22U_0603_6.3V6M  [C_0603]  106.21 56.51 270 top
PC1137  22U_0603_6.3V6M  [C_0603]  105.12 57.63 180 top
PC1138  22U_0603_6.3V6M  [C_0603]  103.73 58.85 0 top
PC1139  22U_0603_6.3V6M  [C_0603]  123.08 56.24 180 top
PC1140  22U_0603_6.3V6M  [C_0603]  124.05 56.31 0 top
PC1141  22U_0603_6.3V6M  [C_0603]  122.36 62.35 180 top
PC1142  22U_0603_6.3V6M  [C_0603]  122.45 59.95 180 top
PC1143  22U_0603_6.3V6M  [C_0603]  83.32 79.77 90 bottom
PC1144  22U_0603_6.3V6M  [C_0603]  84.59 79.77 90 bottom
PC1145  22U_0603_6.3V6M  [C_0603]  85.86 79.77 90 bottom
PC1146  22U_0603_6.3V6M  [C_0603]  122.4 61.15 180 top
PC1147  1U_0201_6.3V6M  [C_0201]  123.31 62.92 0 top
PC1148  1U_0201_6.3V6M  [C_0201]  122.15 66.48 90 top
PC1149  1U_0201_6.3V6M  [C_0201]  123.32 62.3 0 top
PC1150  1U_0201_6.3V6M  [C_0201]  123.52 59.87 0 top
PC1151  1U_0201_6.3V6M  [C_0201]  123.52 59.31 0 top
PC1152  1U_0201_6.3V6M  [C_0201]  121.37 66.57 180 top
PC1153  1U_0201_6.3V6M  [C_0201]  123.52 60.44 0 top
PC1164  1U_0201_6.3V6M  [C_0201]  114.66 64.98 90 top
PC1170  22U_0603_6.3V6M  [C_0603]  86.06 67.43 90 bottom
PC1171  22U_0603_6.3V6M  [C_0603]  86.16 66.33 270 bottom
PC1172  100P_0603_50V8  [C_0603]  87.45 66.33 270 bottom
PC1173  22U_0603_6.3V6M  [C_0603]  84.88 66.34 270 bottom
PC1174  100P_0603_50V8  [C_0603]  87.39 68.81 270 bottom
PC1175  100P_0603_50V8  [C_0603]  87.53 58.59 270 bottom
PC1176  22U_0603_6.3V6M  [C_0603]  87.44 62.28 90 top
PC1177  100P_0603_50V8  [C_0603]  87.45 62.28 90 bottom
PC1178  22U_0603_6.3V6M  [C_0603]  87.53 58.59 270 top
PC1179  22U_0603_6.3V6M  [C_0603]  89.64 62.27 90 top
PC1180  22U_0603_6.3V6M  [C_0603]  85.25 62.28 90 bottom
PC1181  22U_0603_6.3V6M  [C_0603]  85.55 58.63 270 bottom
PC1201  0.01U_0402_25V7K~D  [C_0402]  64.85 107.44 0 bottom
PC1202  2200P 50V K X7R 0603  [C_0603]  8.84 52.03 270 top
PC1203  1500P_0402_50V7K  [C_0402]  9.38 42.61 0 top
PC1204  0.1U_0402_10V7K  [C_0402]  16.93 55.84 180 top
PC1205  100P_0402_50V8J~D  [C_0402]  67.33 111.28 0 bottom
PC1206  220P_0402_50V8J~D  [C_0402]  68.06 110.4 0 top
PC1207  1200P_0402_50V7K  [C_0402]  65.43 110.54 180 bottom
PC1208  1000P_0402_50V7K  [C_0402]  14.45 85.06 270 top
PC1209  0.1U_0402_25V6  [C_0402]  17.66 85.11 270 top
PC1210  1500P_0402_50V7K  [C_0402]  14.86 50.56 180 top
PC1211  100P_0402_50V8J  [C_0402]  68.46 106.8 90 top
PC1212  100P_0402_50V8J  [C_0402]  67.49 103.94 270 bottom
PC1213  1200P_0402_50V7K  [C_0402]  66.58 103.92 270 bottom
PC1214  0.01UF_0402_25V7K  [C_0402]  15.93 54.06 90 top
PC1215  100P_0402_50V8J  [C_0402]  15.63 89.98 90 bottom
PC1216  100P_0402_50V8J  [C_0402]  18.29 88.78 90 bottom
PC1217  1500P_0402_50V7K  [C_0402]  33.23 31.32 180 top
PC1286  0.1U_0402_25V6  [C_0402]  13.2 16.9 180 bottom
PD1  -  [TVNST52302AB0_SOT523-3]  18.99 2.78 180 top
PD2  -  [TVNST52302AB0_SOT523-3]  21.04 2.78 180 top
PD3  BAS40CW SOT-323  [DB3J315E0L_SMINI3-F2-B3]  60.35 76.9 180 top
PD4  -  [PESD5V0U2BT_SOT23-3]  63.38 86.36 180 bottom
PD5  5A_100V 15UA_0.88V_TO227-3  [PDS5100H-13_POWERDI5-3]  44.64 84.22 90 top
PD100  -  [RB520SM-30T2R_EMD2-2]  174.57 115.75 90 bottom
PD901  SDMK0340L-7-F_SOD323-2~D  [SDMK0340L-7-F_SOD323-2]  7.83 23.92 90 top
PD903  -  [RB520SM-30T2R_EMD2-2]  9.53 23.91 90 top
PD904  SDMK0340L-7-F_SOD323-2~D  [SDMK0340L-7-F_SOD323-2]  11.26 23.92 90 top
PD905  BAT54CW-7-F SOT-323  [BAT54CW_SOT323-3]  30.38 26.46 90 top
PD1202  5A_100V 15UA_0.88V_TO227-3  [PDS5100H-13_POWERDI5-3]  6.48 44.98 90 top
PD1205  -  [SDMK0340L-7-F_SOD323-2]  70.52 107.02 270 bottom
PD1801  BAT54CW-7-F SOT-323  [BAT54CW_SOT323-3]  65.5 105.6 90 bottom
PH601  470K_0402_5%  [R_0402]  61.73 61.36 270 bottom
PH602  10K_0402_5%  [R_0402]  68.67 58.23 180 bottom
PH603  470K_0402_5%  [R_0402]  60.97 73.17 0 bottom
PH604  10KB_0402_5%  [R_0402]  80.02 81.55 180 bottom
PH605  10KB_0402_5%  [R_0402]  66.79 74.38 0 bottom
PJP1  PAD-OPEN1X1M  [JUMP_43X39]  123.37 82.76 0 bottom
PJP2  PAD-OPEN1X1M  [JUMP_43X39]  144.28 88.55 270 bottom
PJP3  PAD-OPEN1X3M  [JUMP_43X118]  139.58 88.3 90 bottom
PJP4  PAD-OPEN1X1M  [JUMP_43X39]  156.72 54.76 0 top
PJP7  PAD-OPEN1X1M  [JUMP_43X39]  31.95 88.42 270 top
PJP8  PAD-OPEN 1X3M  [JUMP_43X118]  39.31 95.81 270 top
PJP12  PAD-OPEN1X1M  [JUMP_43X39]  100.21 84.99 270 bottom
PJP14  PAD-OPEN1X2M  [JUMP_43X79]  17.87 43.71 0 top
PJP15  PAD-OPEN1X1M  [JUMP_43X39]  277.63 70.17 90 top
PJP16  PAD-OPEN1X1M  [JUMP_43X39]  273.19 70.63 180 top
PJP17  PAD-OPEN1X2M  [JUMP_43X79]  271.93 67.46 0 top
PJP18  PAD-OPEN1X1M  [JUMP_43X39]  274.07 77.36 90 top
PJP19  PAD-OPEN1X1M  [JUMP_43X39]  305.95 42.8 90 top
PJP20  PAD-OPEN1X1M  [JUMP_43X39]  309.95 73.35 90 top
PJP21  PAD-OPEN1X1M  [JUMP_43X39]  312.32 73.35 90 top
PJP22  PAD-OPEN1X1M  [JUMP_43X39]  300.7 64.88 90 top
PJP31  PAD-OPEN1X3M  [JUMP_43X118]  290.01 33 90 top
PJP32  PAD-OPEN1X1M  [JUMP_43X39]  280.42 38.83 270 bottom
PJP33  PAD-OPEN1X1M  [JUMP_43X39]  278.14 37.91 90 bottom
PJP34  PAD-OPEN1X2M  [JUMP_43X79]  273.94 40.45 270 bottom
PJP35  PAD-OPEN1X1M  [JUMP_43X39]  217.43 17.34 90 top
PJP36  PAD-OPEN1X2M  [JUMP_43X79]  193.43 12.85 270 top
PJP37  PAD-OPEN1X1M  [JUMP_43X39]  278.26 53 0 bottom
PJP38  PAD-OPEN1X1M  [JUMP_43X39]  205.49 9.29 0 top
PJP39  PAD-OPEN1X3M  [JUMP_43X118]  202.57 4.34 270 top
PJP40  PAD-OPEN1X2M  [JUMP_43X79]  194.95 19.53 90 top
PJP41  PAD-OPEN1X3M  [JUMP_43X118]  279.74 46.25 0 bottom
PJP42  PAD-OPEN1X1M  [JUMP_43X39]  271.71 47.64 0 top
PJP100  PAD-OPEN 1X2M~D  [JUMP_43X79]  160.16 114.12 180 top
PJP101  PAD-OPEN 1X2M~D  [JUMP_43X79]  160.59 116.44 0 bottom
PJP102  -  [JUMP_43X118]  148.95 102.06 180 bottom
PJP103  -  [JUMP_43X118]  166.88 101.02 270 bottom
PJP200  -  [JUMP_43X118]  48.37 39.39 270 top
PJP201  -  [JUMP_43X39]  47.44 52.06 0 top
PJP202  PAD-OPEN 1X2M~D  [JUMP_43X79]  40.39 45.1 0 top
PJP301  PAD-OPEN 1X2M~D  [JUMP_43X79]  176.79 98.68 270 bottom
PJP302  -  [JUMP_43X118]  178.29 81.3 180 bottom
PJP391  PAD-OPEN1X1M  [JUMP_43X39]  158.95 42.45 270 top
PJP401  -  [JUMP_43X79]  143.45 103.04 270 top
PJP402  -  [JUMP_43X79]  133.92 103.61 270 top
PJP403  PAD-OPEN1X1M  [JUMP_43X39]  136.17 114.12 0 top
PJP404  PAD-OPEN1X1M  [JUMP_43X39]  134.73 115.81 180 top
PJP501  PAD-OPEN1X1M  [JUMP_43X39]  124.83 111.02 270 top
PJP502  PAD-OPEN1X1M  [JUMP_43X39]  120.43 101.97 270 top
PJP505  PAD-OPEN1X1M  [JUMP_43X39]  198.86 6.21 180 top
PJP506  PAD-OPEN1X1M  [JUMP_43X39]  192.39 8.17 90 top
PJP601  PAD-OPEN 4X4M  [JUMP_43X118]  50.84 65.06 180 bottom
PJP602  PAD-OPEN 1X2M~D  [JUMP_43X79]  55.27 65.16 90 bottom
PJP603  PAD-OPEN1X1M  [JUMP_43X39]  71.59 81.14 180 bottom
PJP901  PAD-OPEN 4X4M  [JUMP_43X118-NPM]  9.25 16.94 90 bottom
PJP1202  -  [JUMP_43X118]  8.89 54.93 270 top
PJPDC1  CVILU_CI0805M1HRC-NH  [CVILU_CI0805M1HRC-NH_5P-T]  58.55 90.6 180 bottom
PL1  FBMJ4516HS720NT_2P  [TAIYO_FBMJ4516HS720NT_2P]  26.52 7.2 270 top
PL2  FBMJ4516HS720NT_2P  [TAIYO_FBMJ4516HS720NT_2P]  24.2 7.19 270 top
PL3  BLM15AG102SN1D_2P  [MURAT_BLM15AG102SN1D_2P]  59.59 90.68 0 top
PL4  FBMJ4516HS720NT_2P  [TAIYO_FBMJ4516HS720NT_2P]  55.97 90.97 180 top
PL100  1.5UH_9A_20%_7X7X3_M  [L_7X7X3_M_2P]  157.49 106.13 270 bottom
PL101  1.5UH_9A_20%_7X7X3_M  [L_7X7X3_M_2P]  166.9 110.29 270 bottom
PL201  1UH_11A_20%_7X7X3_M  [L_7X7X3_M_2P]  52.2 49.5 270 bottom
PL301  0.68UH_7.9A_20%_5X5X3_M  [L_5X5X3_M_2P]  180.85 90.14 270 bottom
PL402  1UH_1277AS-H-1R0N-P2_3.3A_30%  [MAG_MLV-FY12N1R0M-O1L_2P]  139.42 105.76 0 top
PL404  1UH_1277AS-H-1R0N-P2_3.3A_30%  [MAG_MLV-FY12N1R0M-O1L_2P]  128.91 108.22 0 top
PL501  1UH_1277AS-H-1R0N-P2_3.3A_30%  [MAG_MLV-FY12N1R0M-O1L_2P]  123.16 104.31 270 top
PL602  9A Z80 10M 1812_2P  [9A_Z80_1812_2P-NPM]  52.22 65.01 180 bottom
PL610  0.15UH_MMD06CZER15MG_37A_20%  [L_7X7X3_M]  70.85 70.12 180 bottom
PL612  0.15UH_MMD06CZER15MG_37A_20%  [L_7X7X3_M]  70.85 62.5 180 bottom
PL614  0.47UH_MMD05CZR47M_12A_20%  [L_5X5X3_M_2P]  80.86 78.19 180 bottom
PL901  1UH_6.6A_20%_5X5X3_M  [MAGLA_MMD-05CZ-1R0M-M7L_2P]  9.24 19.55 270 bottom
PL902  2.2UH_PCMB103T-2R2MS_13A_20%  [CYNTE_PCMB103T-2R2MS_2P]  21.23 24.61 0 bottom
PL1201  5A_Z120_25M_0805_2P  [C_0805]  15.57 85.78 0 bottom
PL1202  5A_Z120_25M_0805_2P  [C_0805]  15.57 87.5 0 bottom
PQ1  -  [DMN65D8LDW-7_SOT363-6]  60.19 106.12 90 top
PQ2  -  [FDV301N-G_SOT23-3]  63.51 91.12 180 top
PQ3  MMST3904-7-F_SOT323~D  [MMST3904-7-F_SOT323-3]  60.82 89 90 top
PQ4  AON7409_DFN8-5  [FDMC6679AZ_MLP8-5]  47.88 84.6 270 top
PQ5  AO3409_SOT23  [NTR4502PT1G_SOT23-3]  60.69 103.27 90 top
PQ6  L2N7002WT1G_SC70-3  [DMN65D8LW-7_SOT323-3]  57.11 92.8 90 top
PQ7  L2N7002WT1G_SC70-3  [DMN65D8LW-7_SOT323-3]  64.58 103.07 270 top
PQ8  L2N7002WT1G_SC70-3  [DMN65D8LW-7_SOT323-3]  62.23 102.85 270 bottom
PQ9  AON7409_DFN8-5  [FDMC6679AZ_MLP8-5]  49.92 89.55 180 top
PQ501  AON7934_DFN3X3A-8-10  [AON7934_DFN3X3A8-10]  72.01 79.3 0 bottom
PQ904  -  [CSD87351Q5D_SON8-7]  31.15 13.42 180 bottom
PQ905  -  [CSD87351Q5D_SON8-7]  12.55 25.68 90 bottom
PQ906  AON7409_DFN8-5  [FDMC6679AZ_MLP8-5]  30.49 5.73 180 top
PQ909  L2N7002WT1G_SC70-3  [DMN65D8LW-7_SOT323-3]  32.14 29.2 90 top
PQ1201  -  [DMN65D8LDW-7_SOT363-6]  14.95 34.68 0 top
PQ1202  AON7409_DFN8-5  [FDMC6679AZ_MLP8-5]  10.11 46.11 270 top
PQ1203  AO3409_SOT23  [NTR4502PT1G_SOT23-3]  8.07 40.22 90 top
PQ1204  -  [DMN65D8LDW-7_SOT363-6]  13.35 33.46 270 top
PQ1205  L2N7002WT1G_SC70-3  [DMN65D8LW-7_SOT323-3]  20.22 32.67 90 top
PQ1206  AON7409_DFN8-5  [FDMC6679AZ_MLP8-5]  12.58 52.47 0 top
PQ1207  DMN65D8LDW-7_SOT363-6  [DMN66D0LDW-7_SOT363-6]  30.28 36.6 180 top
PQ1208  DMN65D8LDW-7_SOT363-6  [DMN66D0LDW-7_SOT363-6]  27.78 37.19 180 top
PQ1209  -  [DMN65D8LDW-7_SOT363-6]  18.79 53.42 90 top
PQ1210  DMN65D8LDW-7_SOT363-6  [DMN66D0LDW-7_SOT363-6]  28.9 33.64 270 top
PQ1211  DMN65D8LDW-7_SOT363-6  [DMN66D0LDW-7_SOT363-6]  27.78 34.19 180 top
PQ1212  L2N7002WT1G_SC70-3  [DMN65D8LW-7_SOT323-3]  70.21 107.17 180 top
PQ1213  AON7409_DFN8-5  [FDMC6679AZ_MLP8-5]  12.41 50.47 180 top
PQ1214  -  [DMN65D8LDW-7_SOT363-6]  11.39 34.59 0 top
PQ1215  AO3409_SOT23  [NTR4502PT1G_SOT23-3]  3.62 51.17 0 top
PQ1216  L2N7002WT1G_SC70-3  [DMN65D8LW-7_SOT323-3]  9.91 14.94 0 top
PR1  100K_0402_5%  [R_0402]  17.48 3.31 90 top
PR2  1K_0402_5%  [R_0402]  62.12 78.07 90 top
PR3  0_0402_5%  [R_0402]  63.03 92.83 0 top
PR4  2.2K_0402_5%  [R_0402]  64.94 93.74 180 top
PR5  33_0402_5%  [R_0402]  64.94 91.86 90 top
PR6  100K_0402_1%  [R_0402]  57.81 90.67 0 top
PR7  10K_0402_1%  [R_0402]  62.03 92.78 270 top
PR8  15K_0402_1%  [R_0402]  57.82 88.89 90 top
PR10  300K_0402_1%  [R_0402]  56.52 102.96 90 top
PR11  499K_0402_1%  [R_0402]  46.76 79.77 0 top
PR12  499K_0402_1%  [R_0402]  49.92 92.35 180 top
PR13  4.7K_0805_5%  [R_0805]  52.26 89.24 270 top
PR14  100K_0402_5%  [R_0402]  52.08 84.73 0 top
PR15  100K_0402_5%  [R_0402]  56.52 104.73 90 top
PR16  49.9K_0402_1%  [R_0402]  61.55 101.31 0 top
PR17  100K_0402_5%  [R_0402]  63.07 107.59 180 top
PR18  49.9K_0402_1%  [R_0402]  54.97 93.26 0 top
PR19  0_0402_5%  [R0402_0OHM]  61.22 107.56 270 top
PR20  0_0402_5%  [R0402_0OHM]  63.56 104.79 90 top
PR21  0_0402_5%  [R0402_0OHM]  62.22 94.35 90 bottom
PR22  0_0402_5%  [R0402_0OHM]  66.43 96.16 270 bottom
PR23  0_0402_5%  [R0402_0OHM]  60.33 92.5 90 top
PR24  100K_0402_5%  [R_0402]  63.1 106.65 180 top
PR25  0_0402_5%  [R0402_0OHM]  56.16 106.95 0 top
PR26  0_0402_5%  [R0402_0OHM]  67.65 99.78 180 bottom
PR27  100K_0402_5%  [R_0402]  66.73 98.76 0 bottom
PR28  100K_0402_5%  [R_0402]  61.79 103.91 90 bottom
PR29  0_0402_5%  [R0402_0OHM]  65.26 102.19 90 bottom
PR100  0_0603_5%  [R0603_0OHM]  158.37 111.52 0 top
PR102  499K_0402_1%  [R_0402]  171.31 117.69 90 bottom
PR103  499K_0402_1%  [R_0402]  172.16 117.94 0 bottom
PR104  0_0402_5%  [R0402_0OHM]  152.55 111.09 180 top
PR105  0_0402_5%  [R0402_0OHM]  152.55 110.2 180 top
PR106  4.7_1206_5%  [R_1206]  156.28 109.05 0 bottom
PR107  100K_0402_5%  [R_0402]  153.41 116.08 270 top
PR108  1K_0402_5%  [R_0402]  150.62 112.65 270 top
PR111  0_0603_5%  [R0603_0OHM]  164.8 113.27 180 bottom
PR112  4.7_1206_5%  [R_1206]  162.17 110.66 270 bottom
PR113  100K_0402_5%  [R_0402]  170.07 118.42 270 bottom
PR114  0_0402_5%  [R0402_0OHM]  172.8 116.42 270 bottom
PR116  1M_0402_1%  [R_0402]  171.92 115.5 90 bottom
PR117  1K_0402_5%  [R_0402]  172.98 114.65 270 bottom
PR119  0_0402_5%  [R0402_0OHM]  154.31 115.16 90 top
PR120  0_0402_5%  [R0402_0OHM]  169.19 117.51 90 bottom
PR202  4.7_1206_5%  [R_1206]  51.34 49.13 180 top
PR203  0_0603_5%  [R0603_0OHM]  47.27 47.42 0 top
PR204  102K_0402_1%  [R_0402]  45.53 44.65 90 bottom
PR205  0_0402_5%  [R_0402]  41.98 45.56 270 bottom
PR206  100K_0402_1%  [R_0402]  43.76 45.56 270 bottom
PR207  0_0402_5%  [R_0402]  42.87 44.65 90 bottom
PR208  0_0402_5%  [R0402_0OHM]  41.47 51.15 90 bottom
PR209  1M_0402_5%  [R_0402]  39.71 51.16 90 bottom
PR210  0_0402_5%  [R0402_0OHM]  42.34 51.15 90 bottom
PR212  1M_0402_5%  [R_0402]  44.09 51.14 90 bottom
PR302  1M_0402_1%  [R_0402]  184.14 98.57 0 bottom
PR303  4.7_1206_5%  [R_1206]  177.23 90.32 180 bottom
PR304  0_0603_5%  [R0603_0OHM]  176.47 91.97 0 bottom
PR306  21.5K_0402_1%  [R_0402]  185.06 93.11 180 bottom
PR307  0_0402_5%  [R_0402]  185.06 96.73 180 bottom
PR308  1K_0402_5%  [R_0402]  185.06 94 180 bottom
PR310  0_0402_5%  [R_0402]  184.14 95.84 0 bottom
PR311  31.6K_0402_1%  [R_0402]  184.14 94.89 0 bottom
PR312  0_0402_5%  [R0402_0OHM]  184.14 97.68 0 bottom
PR402  0_0402_5%  [R0402_0OHM]  136.56 110.51 0 top
PR403  1M_0402_1%  [R_0402]  137.46 112.3 180 top
PR404  0_0402_5%  [R_0402]  137.4 108.68 0 top
PR405  4.7_0603_5%  [R_0603]  138.14 105.33 90 top
PR406  0_0402_5%  [R0402_0OHM]  127.04 112.87 0 top
PR407  1M_0402_1%  [R_0402]  127.05 113.75 90 top
PR408  0_0402_5%  [R_0402]  125.39 113.22 90 top
PR409  4.7_0603_5%  [R_0603]  127.26 107.71 90 top
PR410  0_0402_5%  [R_0402]  127.03 111.05 0 top
PR411  0_0402_5%  [R_0402]  122.77 113.22 90 top
PR412  0_0402_5%  [R_0402]  144.71 109.52 0 top
PR413  10K_0402_1%  [R_0402]  145.19 112.31 180 top
PR414  10K_0402_1%  [R_0402]  145.19 113.2 180 top
PR415  10K_0402_1%  [R_0402]  143.41 112.57 90 top
PR416  10K_0402_1%  [R_0402]  143.49 114.52 180 top
PR417  10K_0402_1%  [R_0402]  123.63 113.22 90 top
PR418  10K_0402_1%  [R_0402]  124.51 113.22 90 top
PR419  10K_0402_1%  [R_0402]  123.67 114.99 180 top
PR420  10K_0402_1%  [R_0402]  124.49 115 0 top
PR421  0_0402_5%  [R_0402]  145.62 107.74 180 top
PR422  0_0402_5%  [R_0402]  144.71 108.63 0 top
PR423  0_0402_5%  [R0402_0OHM]  133.76 110.44 0 top
PR424  100K_0402_1%  [R_0402]  133.76 111.31 0 top
PR425  0_0402_5%  [R0402_0OHM]  137.4 109.6 0 top
PR426  0_0402_5%  [R0402_0OHM]  127.03 111.96 0 top
PR427  0_0402_5%  [R_0402]  144.71 110.53 0 top
PR428  1M_0402_1%  [R_0402]  133.72 113.18 0 top
PR501  20K_0402_1%  [R_0402]  120.04 108.77 0 top
PR502  4.7_0603_5%  [R_0603]  125.76 104.08 90 top
PR504  0_0402_5%  [R0402_0OHM]  119.69 107.64 0 top
PR505  1M_0402_1%  [R_0402]  120.61 106.73 180 top
PR506  10K_0402_1%  [R_0402]  122.36 109.65 90 top
PR513  0_0402_5%  [R0402_0OHM]  198.5 3.98 180 top
PR514  1M_0402_1%  [R_0402]  198.48 3.11 270 top
PR515  21.5K_0402_1%  [R_0402]  190.99 3.29 0 top
PR516  10.2K_0402_1%  [R_0402]  191.91 2.42 180 top
PR517  100K_0402_5%  [R_0402]  123.25 109.65 90 top
PR601  45.3_0402_1%  [R_0402]  73.76 50.78 0 bottom
PR602  0_0402_5%  [R0402_0OHM]  74.31 46.89 0 top
PR603  0_0402_5%  [R0402_0OHM]  72.6 46.85 0 bottom
PR604  75_0402_1%  [R_0402]  73.76 49.92 0 bottom
PR605  100_0402_1%  [R_0402]  73.76 49.03 0 bottom
PR606  0_0402_5%  [R0402_0OHM]  68.78 80.28 180 bottom
PR608  78.7K_0402_1%  [R_0402]  73.42 47.11 270 top
PR610  10K_0402_1%  [R_0402]  72.22 56.15 270 top
PR611  48.7K_0402_1%  [R_0402]  71.63 46.21 0 top
PR612  1.91K_0402_1%  [R_0402]  74.68 52.57 180 bottom
PR613  88.7K_0402_1%  [R_0402]  71.25 52.34 90 bottom
PR614  0_0402_5%  [R0402_0OHM]  74.68 51.68 180 bottom
PR616  0_0402_5%  [R0402_0OHM]  74.44 53.49 180 top
PR617  3.92K_0402_1%  [R_0402]  68.25 53.21 0 bottom
PR618  49.9_0402_1%  [R_0402]  74.63 50.82 180 top
PR619  2.2_0603_5%  [R_0603]  65.73 77.11 0 top
PR620  0_0402_5%  [R0402_0OHM]  73.1 55.63 270 top
PR621  316_0402_1%  [R_0402]  70.42 56.98 270 top
PR622  1.91K_0402_1%  [R_0402]  69.55 56.99 270 top
PR623  2K_0402_1%  [R_0402]  70.44 55.2 180 top
PR624  3.65K_0603_1%  [R_0603]  75.87 42.82 180 top
PR625  0_0402_5%  [R0402_0OHM]  74.43 49.92 180 top
PR626  10_0402_1%  [R_0402]  74.25 49.04 180 top
PR627  4.7_1206_5%  [R_1206]  76.5 77.79 180 top
PR628  4.42K_0402_1%  [R_0402]  68.7 55.18 90 bottom
PR629  93.1K_0402_1%  [R_0402]  66.5 51.8 180 bottom
PR630  2.49K_0402_1%  [R_0402]  70.84 47.2 0 bottom
PR631  27.4K_0402_1%  [R_0402]  71.3 57.4 0 top
PR632  1K_0402_1%  [R_0402]  66.88 56.94 180 top
PR633  11K_0402_1%  [R_0402]  67.77 55.18 90 bottom
PR635  10K_0402_1%  [R_0402]  65.59 49.12 90 bottom
PR636  665_0402_1%  [R_0402]  71.77 43.9 0 top
PR638  365_0402_1%  [R_0402]  66.88 56.08 270 top
PR639  3.6K_0402_1%  [R_0402]  64.14 47.19 90 bottom
PR640  365_0402_1%  [R_0402]  62.8 47 180 top
PR641  1K_0402_1%  [R_0402]  73.57 44.79 270 top
PR642  2.61K_0402_1%  [R_0402]  74.41 41.76 0 top
PR643  11K_0402_1%  [R_0402]  72.67 43.05 270 top
PR644  1K_0402_1%  [R_0402]  61.03 46.09 90 top
PR645  316_0402_1%  [R_0402]  60.9 53.37 0 top
PR646  316_0402_1%  [R_0402]  67.36 43.83 270 bottom
PR647  27.4K_0402_1%  [R_0402]  66.47 50.03 270 bottom
PR648  1.5K_0402_1%  [R_0402]  62.75 51.8 90 top
PR649  1.62K_0402_1%  [R_0402]  67.34 44.68 0 bottom
PR650  2K_0402_1%  [R_0402]  62.74 53.54 90 top
PR651  127K_0402_1%  [R_0402]  68.06 47.07 90 bottom
PR652  2K_0402_1%  [R_0402]  66.49 44.7 270 bottom
PR656  11K_0402_1%  [R_0402]  61.04 48.76 270 top
PR657  4.42K_0402_1%  [R_0402]  60.17 49.1 180 top
PR659  0_0402_5%  [R0402_0OHM]  61.85 72.92 0 top
PR660  2.2_0603_5%  [R_0603]  56.88 70.62 0 top
PR661  3.65K_0603_1%  [R_0603]  58.7 48.05 0 top
PR662  5.11K_0402_1%  [R_0402]  56.98 73.2 180 bottom
PR663  4.7_1206_5%  [R_1206]  64.65 69.11 90 top
PR671  0_0402_5%  [R0402_0OHM]  63.25 65.93 90 bottom
PR672  2.2_0603_5%  [R_0603]  54.87 65.17 0 top
PR674  3.65K_0603_1%  [R_0603]  64.78 55.26 90 bottom
PR676  4.7_1206_5%  [R_1206]  64.9 66.95 0 top
PR678  100_0402_1%  [R_0402]  73.56 51.69 90 top
PR679  0_0402_5%  [R0402_0OHM]  67.72 75.29 180 bottom
PR680  5.11K_0402_1%  [R_0402]  58.43 67.2 0 bottom
PR681  5.11K_0402_1%  [R_0402]  62.74 74.36 90 top
PR682  5.11K_0402_1%  [R_0402]  63.58 66.44 180 top
PR901  0.01_1206_1%  [R_1206_4P-D]  5.45 18.26 270 bottom
PR909  3.3_0402_1%  [R_0402]  16.22 23.04 270 top
PR910  3.3_0402_1%  [R_0402]  17.11 23.04 270 top
PR914  3.3_0603_1%  [R_0603]  19.56 21.93 90 top
PR915  4.7_0402_5%  [R_0402]  20.33 18.8 180 bottom
PR916  1_0805_5%~D  [R_0805]  13.04 21.91 180 top
PR917  0.005_1206_1%  [R_1206_4P-D]  29.7 11.31 270 top
PR918  100K_0402_1%  [R_0402]  12.33 19.59 0 bottom
PR919  0_0402_5%  [R_0402]  13.21 18.57 270 top
PR920  0_0402_5%  [R0402_0OHM]  12.29 16.73 0 top
PR921  4.7_0603_5%  [R_0603]  22.82 17.81 0 top
PR922  0_0402_5%  [R0402_0OHM]  12.29 15.84 0 top
PR923  4.7_1206_5%  [R_1206]  21.73 25.82 180 top
PR924  4.7_1206_5%  [R_1206]  31.28 23.12 270 top
PR925  154K_0402_1%  [R_0402]  31.83 30.2 180 top
PR926  0_0402_5%  [R0402_0OHM]  12.29 14.79 0 top
PR927  1M_0402_1%  [R_0402]  35.14 28.73 90 top
PR928  0_0402_5%  [R0402_0OHM]  12.29 13.92 0 top
PR929  0_0402_5%  [R0402_0OHM]  23.42 16.74 0 bottom
PR930  100K_0402_1%  [R_0402]  13.55 11.56 180 top
PR931  100K_0402_1%  [R_0402]  12.65 10.7 0 top
PR932  105K_0402_1%  [R_0402]  17.73 14.88 180 bottom
PR933  100K_0402_1%  [R_0402]  15.54 11.47 90 top
PR934  499_0402_1%  [R_0402]  16.4 12.39 270 top
PR935  0_0402_5%  [R0402_0OHM]  18.17 9.16 0 top
PR936  0_0402_5%  [R0402_0OHM]  19.11 12.39 270 top
PR937  2.2_0402_1%  [R_0402]  23.31 14.63 0 top
PR938  2.2_0402_1%  [R_0402]  23.31 13.76 0 top
PR939  0_0402_5%  [R0402_0OHM]  34.24 27.09 180 top
PR940  100_0402_5%  [R_0402]  21.87 11.49 90 top
PR941  0_0402_5%  [R0402_0OHM]  34.27 25.84 180 top
PR942  0_0402_5%  [R0402_0OHM]  31.83 28.21 180 top
